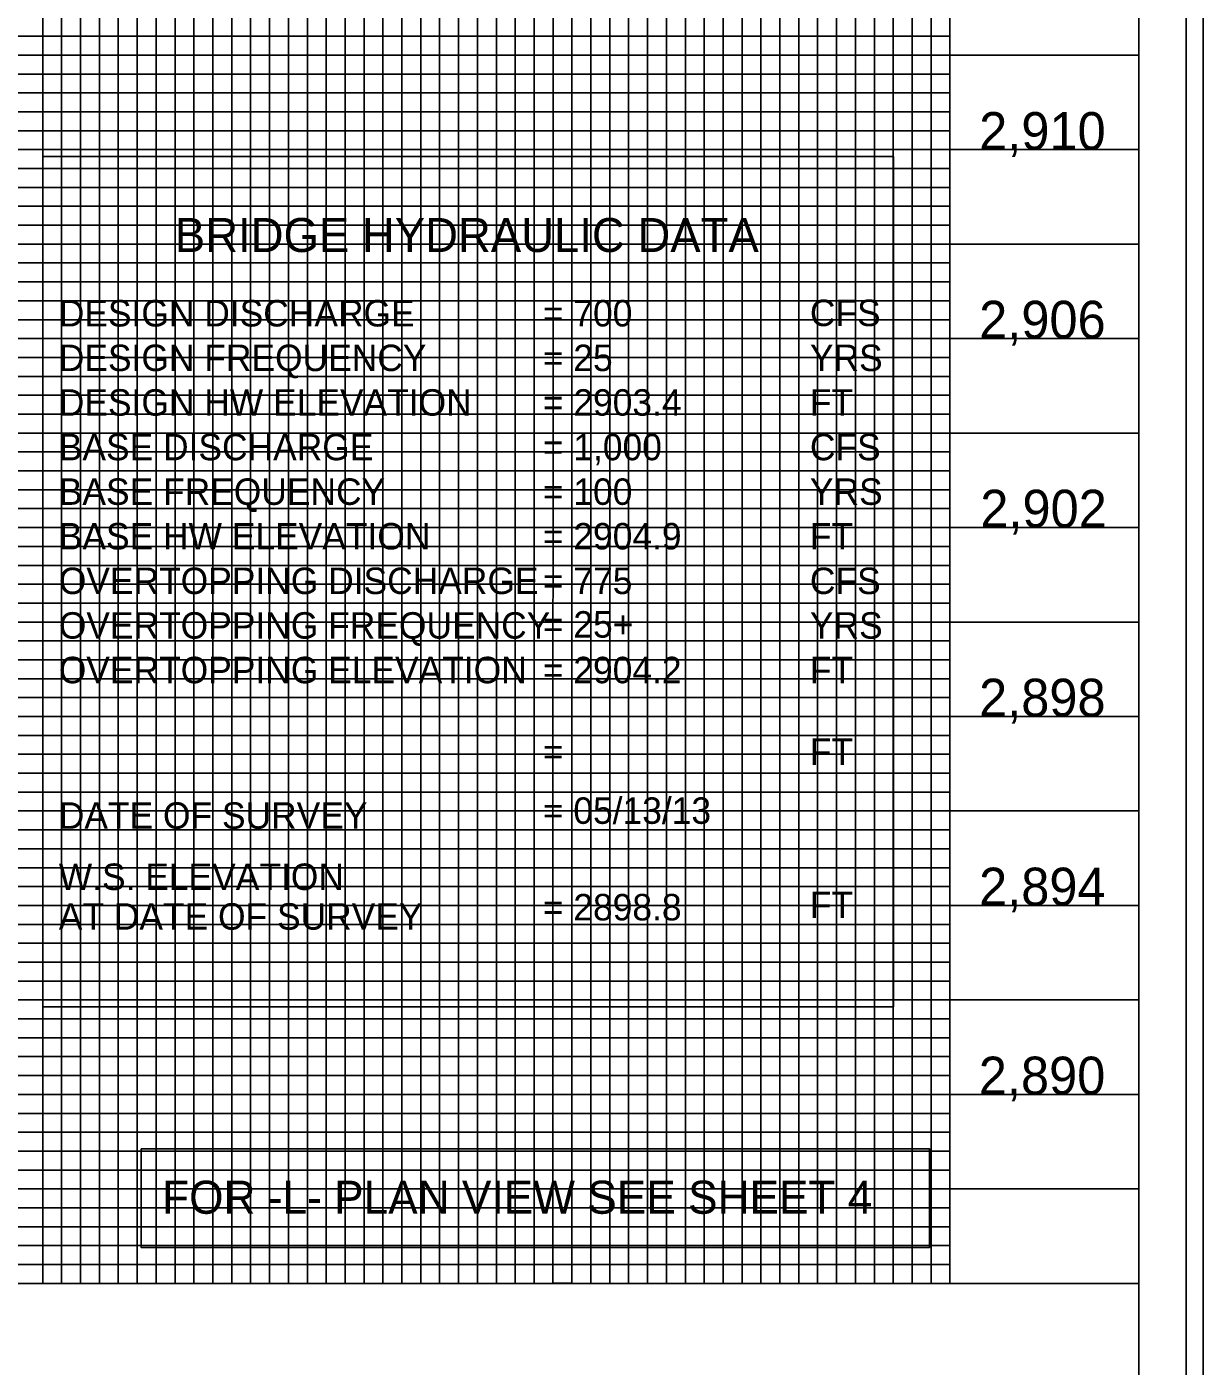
# Model space of a CAD drawing. Extents: x 1191114 to 1192543, y 893004 to 894332.
# Drawn here: x 1191714.7 to 1191839.2, y 894113.5 to 894255.3 of the extents above; entities that cross this region are included whole.
import ezdxf

# ---------------------------------------------------------------- set-up
doc = ezdxf.new("R2010")
doc.units = 0
for name, color, linetype in [('Exist Vertical Profile Ground Line', 7, 'Continuous'), ('Prop Grid Mask', 7, 'Continuous'), ('Prop VPI Ditch Grade Right Label', 7, 'Continuous'), ('Prop VPI Label', 7, 'Continuous'), ('Sheet DOT Grid CELL', 7, 'Continuous'), ('Sheet Layout Profile Border Port 1', 7, 'Continuous'), ('Sheet Plot Border Inside CELL', 7, 'Continuous'), ('Sheet Plot Border Outside CELL', 7, 'Continuous'), ('Sheet Profile CELL', 7, 'Continuous'), ('Sheet Profile Grid Major CELL', 7, 'Continuous'), ('Sheet Profile Grid Middle CELL', 7, 'Continuous'), ('Sheet Profile Grid Minor CELL', 7, 'Continuous')]:
    doc.layers.add(name, color=color, linetype=linetype)

msp = doc.modelspace()

# ---------------------------------------------------------------- linework, layer by layer
at = {"layer": 'Prop Grid Mask'}
for points in [[(1191716.41, 894151.56), (1191806.41, 894151.56), (1191806.41, 894241.56), (1191716.41, 894241.56)], [(1191726.8, 894136.54), (1191810.23, 894136.54), (1191810.23, 894126.11), (1191726.8, 894126.11)]]:
    msp.add_lwpolyline(points, close=True, dxfattribs=at)
at = {"layer": 'Sheet DOT Grid CELL'}
for p, q in [((1191732.39, 894122.3), (1191732.39, 894322.3)), ((1191752.39, 894122.3), (1191752.39, 894267.28)), ((1191772.39, 894122.3), (1191772.39, 894267.28)), ((1191792.39, 894122.3), (1191792.39, 894267.28)), ((1191812.39, 894122.3), (1191812.39, 894267.28)), ((1191832.39, 894242.3), (1191232.39, 894242.3)), ((1191832.39, 894222.3), (1191232.39, 894222.3)), ((1191832.39, 894202.3), (1191232.39, 894202.3)), ((1191832.39, 894182.3), (1191232.39, 894182.3)), ((1191832.39, 894162.3), (1191232.39, 894162.3)), ((1191832.39, 894142.3), (1191232.39, 894142.3))]:
    msp.add_line(p, q, dxfattribs=at)
at = {"layer": 'Sheet Layout Profile Border Port 1'}
msp.add_lwpolyline([(1191252.39, 894322.3), (1191252.39, 894122.3), (1191812.39, 894122.3), (1191812.39, 894267.28), (1191752.37, 894267.28), (1191752.37, 894322.3)], close=True, dxfattribs=at)
at = {"layer": 'Sheet Plot Border Inside CELL'}
msp.add_lwpolyline([(1191170.79, 893901.28), (1191837.39, 893901.28), (1191837.39, 894323.32), (1191170.79, 894323.32)], close=True, dxfattribs=at)
at = {"layer": 'Sheet Plot Border Outside CELL'}
msp.add_lwpolyline([(1191165.59, 893892.3), (1191839.19, 893892.3), (1191839.19, 894332.3), (1191165.59, 894332.3)], close=True, dxfattribs=at)
at = {"layer": 'Sheet Profile CELL'}
msp.add_line((1191232.39, 894122.3), (1191832.39, 894122.3), dxfattribs=at)
msp.add_lwpolyline([(1191832.39, 894322.3), (1191232.39, 894322.3), (1191232.39, 893902.3), (1191832.39, 893902.3)], close=True, dxfattribs=at)
at = {"layer": 'Sheet Profile Grid Major CELL'}
for points in [[(1191532.39, 894122.3), (1191552.39, 894122.3), (1191552.39, 894322.3), (1191572.39, 894322.3), (1191572.39, 894122.3), (1191592.39, 894122.3), (1191592.39, 894322.3), (1191612.39, 894322.3), (1191612.39, 894122.3), (1191632.39, 894122.3), (1191632.39, 894322.3), (1191652.39, 894322.3), (1191652.39, 894122.3), (1191672.39, 894122.3), (1191672.39, 894322.3), (1191692.39, 894322.3), (1191692.39, 894122.3), (1191712.39, 894122.3), (1191712.39, 894322.3), (1191732.39, 894322.3), (1191732.39, 894122.3), (1191752.39, 894122.3), (1191752.39, 894322.3), (1191762.91, 894322.3)], [(1191772.39, 894267.28), (1191772.39, 894122.3), (1191792.39, 894122.3), (1191792.39, 894122.3), (1191792.39, 894267.28)], [(1191812.39, 894267.28), (1191812.39, 894122.3), (1191832.39, 894122.3), (1191832.39, 894262.3)], [(1191832.39, 894242.3), (1191232.39, 894242.3), (1191232.39, 894222.3), (1191832.39, 894222.3)], [(1191832.39, 894202.3), (1191232.39, 894202.3), (1191232.39, 894182.3), (1191832.39, 894182.3)], [(1191832.39, 894162.3), (1191232.39, 894162.3), (1191232.39, 894162.3), (1191232.39, 894142.3), (1191832.39, 894142.3)]]:
    msp.add_lwpolyline(points, dxfattribs=at)
at = {"layer": 'Sheet Profile Grid Middle CELL'}
for points in [[(1191542.39, 894122.3), (1191562.39, 894122.3), (1191562.39, 894322.3), (1191582.39, 894322.3), (1191582.39, 894122.3), (1191602.39, 894122.3), (1191602.39, 894322.3), (1191622.39, 894322.3), (1191622.39, 894122.3), (1191642.39, 894122.3), (1191642.39, 894322.3), (1191662.39, 894322.3), (1191662.39, 894122.3), (1191682.39, 894122.3), (1191682.39, 894322.3), (1191702.39, 894322.3), (1191702.39, 894122.3), (1191722.39, 894122.3), (1191722.39, 894322.3), (1191742.39, 894322.3), (1191742.39, 894122.3), (1191762.39, 894122.3), (1191762.39, 894267.28)], [(1191762.39, 894227.42), (1191762.39, 894122.3), (1191782.39, 894122.3), (1191782.39, 894267.28)], [(1191782.39, 894227.42), (1191782.39, 894122.3), (1191802.39, 894122.3), (1191802.39, 894267.28)], [(1191832.39, 894252.3), (1191232.39, 894252.3), (1191232.39, 894232.3), (1191762.39, 894232.3)], [(1191762.39, 894232.3), (1191832.39, 894232.3)], [(1191832.39, 894212.3), (1191232.39, 894212.3), (1191232.39, 894192.3), (1191832.39, 894192.3)], [(1191832.39, 894172.3), (1191232.39, 894172.3), (1191232.39, 894152.3), (1191832.39, 894152.3)], [(1191832.39, 894132.3), (1191232.39, 894132.3)]]:
    msp.add_lwpolyline(points, dxfattribs=at)
at = {"layer": 'Sheet Profile Grid Minor CELL'}
for p, q in [((1191812.39, 894248.3), (1191252.39, 894248.3)), ((1191252.39, 894246.3), (1191812.39, 894246.3)), ((1191812.39, 894238.3), (1191252.39, 894238.3)), ((1191252.39, 894236.3), (1191812.39, 894236.3)), ((1191812.39, 894228.3), (1191252.39, 894228.3)), ((1191252.39, 894226.3), (1191812.39, 894226.3)), ((1191812.39, 894224.3), (1191252.39, 894224.3)), ((1191252.39, 894220.3), (1191812.39, 894220.3)), ((1191812.39, 894218.3), (1191252.39, 894218.3)), ((1191252.39, 894216.3), (1191812.39, 894216.3)), ((1191812.39, 894214.3), (1191252.39, 894214.3)), ((1191252.39, 894210.3), (1191812.39, 894210.3)), ((1191812.39, 894208.3), (1191252.39, 894208.3)), ((1191252.39, 894206.3), (1191812.39, 894206.3)), ((1191812.39, 894204.3), (1191252.39, 894204.3)), ((1191252.39, 894200.3), (1191812.39, 894200.3)), ((1191812.39, 894198.3), (1191252.39, 894198.3)), ((1191252.39, 894196.3), (1191812.39, 894196.3)), ((1191812.39, 894194.3), (1191252.39, 894194.3)), ((1191252.39, 894190.3), (1191812.39, 894190.3)), ((1191812.39, 894188.3), (1191252.39, 894188.3)), ((1191252.39, 894186.3), (1191812.39, 894186.3)), ((1191812.39, 894184.3), (1191252.39, 894184.3)), ((1191252.39, 894180.3), (1191812.39, 894180.3)), ((1191812.39, 894178.3), (1191252.39, 894178.3)), ((1191252.39, 894176.3), (1191812.39, 894176.3)), ((1191812.39, 894174.3), (1191252.39, 894174.3)), ((1191252.39, 894170.3), (1191812.39, 894170.3)), ((1191812.39, 894168.3), (1191252.39, 894168.3)), ((1191812.39, 894166.3), (1191252.39, 894166.3)), ((1191812.39, 894164.3), (1191252.39, 894164.3)), ((1191252.39, 894160.3), (1191812.39, 894160.3)), ((1191812.39, 894158.3), (1191252.39, 894158.3)), ((1191252.39, 894156.3), (1191812.39, 894156.3)), ((1191812.39, 894154.3), (1191252.39, 894154.3)), ((1191252.39, 894150.3), (1191812.39, 894150.3)), ((1191812.39, 894148.3), (1191252.39, 894148.3)), ((1191252.39, 894146.3), (1191812.39, 894146.3)), ((1191812.39, 894144.3), (1191252.39, 894144.3)), ((1191252.39, 894140.3), (1191812.39, 894140.3)), ((1191812.39, 894138.3), (1191252.39, 894138.3)), ((1191252.39, 894136.3), (1191812.39, 894136.3)), ((1191812.39, 894134.3), (1191252.39, 894134.3)), ((1191252.39, 894130.3), (1191812.39, 894130.3)), ((1191812.39, 894128.3), (1191252.39, 894128.3)), ((1191252.39, 894126.3), (1191812.39, 894126.3))]:
    msp.add_line(p, q, dxfattribs=at)
for points in [[(1191714.39, 894122.3), (1191716.39, 894122.3), (1191716.39, 894322.3)], [(1191718.39, 894322.3), (1191718.39, 894122.3), (1191720.39, 894122.3), (1191720.39, 894322.3)], [(1191724.39, 894322.3), (1191724.39, 894122.3), (1191726.39, 894122.3), (1191726.39, 894322.3)], [(1191728.39, 894322.3), (1191728.39, 894122.3), (1191730.39, 894122.3), (1191730.39, 894322.3)], [(1191734.39, 894322.3), (1191734.39, 894122.3), (1191736.39, 894122.3), (1191736.39, 894322.3)], [(1191738.39, 894322.3), (1191738.39, 894122.3), (1191740.39, 894122.3), (1191740.39, 894322.3)], [(1191744.39, 894322.3), (1191744.39, 894122.3), (1191746.39, 894122.3), (1191746.39, 894322.3)], [(1191748.39, 894322.3), (1191748.39, 894122.3), (1191750.39, 894122.3), (1191750.39, 894322.3)], [(1191754.39, 894267.28), (1191754.39, 894122.3), (1191756.39, 894122.3), (1191756.39, 894267.28)], [(1191758.39, 894267.28), (1191758.39, 894122.3), (1191760.39, 894122.3), (1191760.39, 894267.28)], [(1191764.39, 894267.28), (1191764.39, 894122.3), (1191764.39, 894122.3), (1191766.39, 894122.3), (1191768.39, 894122.3), (1191768.39, 894267.28)], [(1191766.39, 894267.28), (1191766.39, 894122.3)], [(1191770.39, 894267.28), (1191770.35, 894122.32), (1191772.35, 894122.32), (1191774.39, 894122.3), (1191774.39, 894267.28)], [(1191774.39, 894227.42), (1191774.39, 894122.3), (1191776.39, 894122.3), (1191776.39, 894267.28)], [(1191778.39, 894267.28), (1191778.39, 894122.3), (1191780.39, 894122.3), (1191780.39, 894267.28)], [(1191784.39, 894267.28), (1191784.39, 894122.3), (1191786.39, 894122.3), (1191786.39, 894267.28)], [(1191788.39, 894267.28), (1191788.39, 894122.3), (1191790.39, 894122.3), (1191790.39, 894267.28)], [(1191794.39, 894267.28), (1191794.39, 894122.3), (1191796.39, 894122.3), (1191796.39, 894267.28)], [(1191798.39, 894267.28), (1191798.39, 894122.3), (1191800.39, 894122.3), (1191800.39, 894267.28)], [(1191804.39, 894267.28), (1191804.39, 894122.3), (1191806.39, 894122.3), (1191806.39, 894267.28)], [(1191808.39, 894267.28), (1191808.39, 894122.3), (1191810.39, 894122.3), (1191810.39, 894267.28)], [(1191812.39, 894254.3), (1191252.39, 894254.3), (1191252.39, 894250.3), (1191812.39, 894250.3)], [(1191812.39, 894244.3), (1191252.39, 894244.3), (1191252.39, 894240.3), (1191812.39, 894240.3)], [(1191812.39, 894234.3), (1191252.39, 894234.3), (1191252.39, 894230.3), (1191812.39, 894230.3)], [(1191812.39, 894124.3), (1191252.39, 894124.3)]]:
    msp.add_lwpolyline(points, dxfattribs=at)

# ---------------------------------------------------------------- texts
at = {"layer": 'Exist Vertical Profile Ground Line'}
for s, p in [('2,910', (1191815.48, 894242.27)), ('2,906', (1191815.48, 894222.3)), ('2,902', (1191815.6, 894202.3)), ('2,898', (1191815.47, 894182.3)), ('2,894', (1191815.47, 894162.3)), ('2,890', (1191815.44, 894142.3))]:
    msp.add_text(s, height=4, dxfattribs=at).set_placement(p)
at = {"layer": 'Prop VPI Ditch Grade Right Label'}
for s, height, p in [('BRIDGE HYDRAULIC DATA', 3.6, (1191730.37, 894231.46)), ('DESIGN DISCHARGE', 2.8, (1191718.09, 894223.58)), ('= 700', 2.8, (1191769.31, 894223.58)), ('CFS', 2.8, (1191797.57, 894223.62)), ('DESIGN FREQUENCY', 2.8, (1191718.09, 894218.86)), ('= 25', 2.8, (1191769.31, 894218.86)), ('YRS', 2.8, (1191797.57, 894218.86)), ('DESIGN HW ELEVATION', 2.8, (1191718.09, 894214.14)), ('= 2903.4', 2.8, (1191769.31, 894214.14)), ('FT', 2.8, (1191797.57, 894214.14)), ('BASE DISCHARGE', 2.8, (1191718.09, 894209.42)), ('= 1,000', 2.8, (1191769.31, 894209.42)), ('CFS', 2.8, (1191797.57, 894209.42)), ('BASE FREQUENCY', 2.8, (1191718.09, 894204.7)), ('= 100', 2.8, (1191769.31, 894204.7)), ('YRS', 2.8, (1191797.57, 894204.7)), ('BASE HW ELEVATION', 2.8, (1191718.09, 894199.98)), ('= 2904.9', 2.8, (1191769.31, 894199.98)), ('FT', 2.8, (1191797.57, 894199.98)), ('OVERTOPPING DISCHARGE', 2.8, (1191718.09, 894195.26)), ('= 775', 2.8, (1191769.31, 894195.26)), ('CFS', 2.8, (1191797.57, 894195.26)), ('OVERTOPPING FREQUENCY', 2.8, (1191718.09, 894190.54)), ('= 25+', 2.8, (1191769.31, 894190.65)), ('YRS', 2.8, (1191797.57, 894190.54)), ('OVERTOPPING ELEVATION', 2.8, (1191718.09, 894185.82)), ('= 2904.2', 2.8, (1191769.31, 894185.82)), ('FT', 2.8, (1191797.57, 894185.82)), ('=         ', 2.8, (1191769.31, 894177.18)), ('FT', 2.8, (1191797.57, 894177.18)), ('= 05/13/13', 2.8, (1191769.31, 894170.94)), ('DATE OF SURVEY', 2.8, (1191718.09, 894170.42)), ('W.S. ELEVATION', 2.8, (1191718.09, 894163.94)), ('FT', 2.8, (1191797.57, 894160.96)), ('AT DATE OF SURVEY', 2.8, (1191718.09, 894159.74)), ('= 2898.8', 2.8, (1191769.31, 894160.72))]:
    msp.add_text(s, height=height, dxfattribs=at).set_placement(p)
at = {"layer": 'Prop VPI Label'}
msp.add_text('FOR -L- PLAN VIEW SEE SHEET 4', height=3.5, rotation=360, dxfattribs=at).set_placement((1191729.02, 894129.67))

doc.saveas('drawing.dxf')
